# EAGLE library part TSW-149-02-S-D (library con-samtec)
THROUGH-HOLE .025" SQ POST HEADER Source: Samtec TSW.pdf
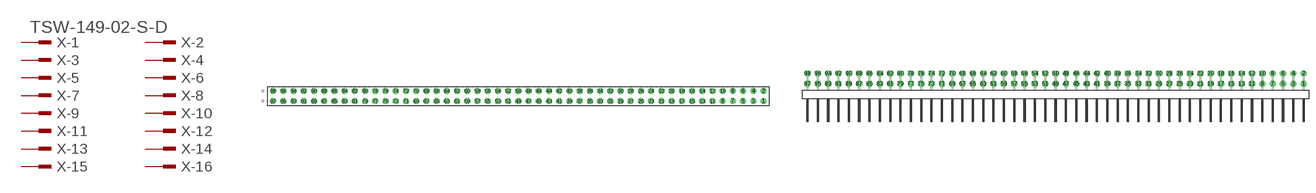
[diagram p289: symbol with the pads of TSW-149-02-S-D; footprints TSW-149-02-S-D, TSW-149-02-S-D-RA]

Designator prefix X; gates -1=MPINV -2=MPIN -3=MPIN -4=MPIN -5=MPIN -6=MPIN -7=MPIN -8=MPIN -9=MPIN -10=MPIN -11=MPIN -12=MPIN -13=MPIN -14=MPIN -15=MPIN -16=MPIN -17=MPIN -18=MPIN -19=MPIN -20=MPIN -21=MPIN -22=MPIN -23=MPIN -24=MPIN -25=MPIN -26=MPIN -27=MPIN -28=MPIN -29=MPIN -30=MPIN -31=MPIN -32=MPIN -33=MPIN -34=MPIN -35=MPIN -36=MPIN -37=MPIN -38=MPIN -39=MPIN -40=MPIN -41=MPIN -42=MPIN -43=MPIN -44=MPIN -45=MPIN -46=MPIN -47=MPIN -48=MPIN -49=MPIN -50=MPIN -51=MPIN -52=MPIN -53=MPIN -54=MPIN -55=MPIN -56=MPIN -57=MPIN -58=MPIN -59=MPIN -60=MPIN -61=MPIN -62=MPIN -63=MPIN -64=MPIN -65=MPIN -66=MPIN -67=MPIN -68=MPIN -69=MPIN -70=MPIN -71=MPIN -72=MPIN -73=MPIN -74=MPIN -75=MPIN -76=MPIN -77=MPIN -78=MPIN -79=MPIN -80=MPIN -81=MPIN -82=MPIN -83=MPIN -84=MPIN -85=MPIN -86=MPIN -87=MPIN -88=MPIN -89=MPIN -90=MPIN -91=MPIN -92=MPIN -93=MPIN -94=MPIN -95=MPIN -96=MPIN -97=MPIN -98=MPIN

## TSW-149-02-S-D (OC_FARNELL: unknown; OC_NEWARK: unknown)  [TSW-149-02-S-D]
1  -1:1  pas
2  -2:1  pas
3  -3:1  pas
4  -4:1  pas
5  -5:1  pas
6  -6:1  pas
7  -7:1  pas
8  -8:1  pas
9  -9:1  pas
10  -10:1  pas
11  -11:1  pas
12  -12:1  pas
13  -13:1  pas
14  -14:1  pas
15  -15:1  pas
16  -16:1  pas
17  -17:1  pas
18  -18:1  pas
19  -19:1  pas
20  -20:1  pas
21  -21:1  pas
22  -22:1  pas
23  -23:1  pas
24  -24:1  pas
25  -25:1  pas
26  -26:1  pas
27  -27:1  pas
28  -28:1  pas
29  -29:1  pas
30  -30:1  pas
31  -31:1  pas
32  -32:1  pas
33  -33:1  pas
34  -34:1  pas
35  -35:1  pas
36  -36:1  pas
37  -37:1  pas
38  -38:1  pas
39  -39:1  pas
40  -40:1  pas
41  -41:1  pas
42  -42:1  pas
43  -43:1  pas
44  -44:1  pas
45  -45:1  pas
46  -46:1  pas
47  -47:1  pas
48  -48:1  pas
49  -49:1  pas
50  -50:1  pas
51  -51:1  pas
52  -52:1  pas
53  -53:1  pas
54  -54:1  pas
55  -55:1  pas
56  -56:1  pas
57  -57:1  pas
58  -58:1  pas
59  -59:1  pas
60  -60:1  pas
61  -61:1  pas
62  -62:1  pas
63  -63:1  pas
64  -64:1  pas
65  -65:1  pas
66  -66:1  pas
67  -67:1  pas
68  -68:1  pas
69  -69:1  pas
70  -70:1  pas
71  -71:1  pas
72  -72:1  pas
73  -73:1  pas
74  -74:1  pas
75  -75:1  pas
76  -76:1  pas
77  -77:1  pas
78  -78:1  pas
79  -79:1  pas
80  -80:1  pas
81  -81:1  pas
82  -82:1  pas
83  -83:1  pas
84  -84:1  pas
85  -85:1  pas
86  -86:1  pas
87  -87:1  pas
88  -88:1  pas
89  -89:1  pas
90  -90:1  pas
91  -91:1  pas
92  -92:1  pas
93  -93:1  pas
94  -94:1  pas
95  -95:1  pas
96  -96:1  pas
97  -97:1  pas
98  -98:1  pas

## TSW-149-02-S-D-RA (OC_FARNELL: unknown; OC_NEWARK: unknown)  [TSW-149-02-S-D-RA]
Pads as for TSW-149-02-S-D

## Footprint TSW-149-02-S-D (pad centres in mm)
THROUGH-HOLE .025" SQ POST HEADER Source: Samtec TSW.pdf
drill 1 pad 1.5 octagon: 1 60.96,-1.27; 2 60.96,1.27; 3 58.42,-1.27; 4 58.42,1.27; 5 55.88,-1.27; 6 55.88,1.27; 7 53.34,-1.27; 8 53.34,1.27; 9 50.8,-1.27; 10 50.8,1.27; 11 48.26,-1.27; 12 48.26,1.27; 13 45.72,-1.27; 14 45.72,1.27; 15 43.18,-1.27; 16 43.18,1.27; 17 40.64,-1.27; 18 40.64,1.27; 19 38.1,-1.27; 20 38.1,1.27; 21 35.56,-1.27; 22 35.56,1.27; 23 33.02,-1.27; 24 33.02,1.27; 25 30.48,-1.27; 26 30.48,1.27; 27 27.94,-1.27; 28 27.94,1.27; 29 25.4,-1.27; 30 25.4,1.27; 31 22.86,-1.27; 32 22.86,1.27; 33 20.32,-1.27; 34 20.32,1.27; 35 17.78,-1.27; 36 17.78,1.27; 37 15.24,-1.27; 38 15.24,1.27; 39 12.7,-1.27; 40 12.7,1.27; 41 10.16,-1.27; 42 10.16,1.27; 43 7.62,-1.27; 44 7.62,1.27; 45 5.08,-1.27; 46 5.08,1.27; 47 2.54,-1.27; 48 2.54,1.27; 49 0,-1.27; 50 0,1.27; 51 -2.54,-1.27; 52 -2.54,1.27; 53 -5.08,-1.27; 54 -5.08,1.27; 55 -7.62,-1.27; 56 -7.62,1.27; 57 -10.16,-1.27; 58 -10.16,1.27; 59 -12.7,-1.27; 60 -12.7,1.27; 61 -15.24,-1.27; 62 -15.24,1.27; 63 -17.78,-1.27; 64 -17.78,1.27; 65 -20.32,-1.27; 66 -20.32,1.27; 67 -22.86,-1.27; 68 -22.86,1.27; 69 -25.4,-1.27; 70 -25.4,1.27; 71 -27.94,-1.27; 72 -27.94,1.27; 73 -30.48,-1.27; 74 -30.48,1.27; 75 -33.02,-1.27; 76 -33.02,1.27; 77 -35.56,-1.27; 78 -35.56,1.27; 79 -38.1,-1.27; 80 -38.1,1.27; 81 -40.64,-1.27; 82 -40.64,1.27; 83 -43.18,-1.27; 84 -43.18,1.27; 85 -45.72,-1.27; 86 -45.72,1.27; 87 -48.26,-1.27; 88 -48.26,1.27; 89 -50.8,-1.27; 90 -50.8,1.27; 91 -53.34,-1.27; 92 -53.34,1.27; 93 -55.88,-1.27; 94 -55.88,1.27; 95 -58.42,-1.27; 96 -58.42,1.27; 97 -60.96,-1.27; 98 -60.96,1.27

## Footprint TSW-149-02-S-D-RA (pad centres in mm)
THROUGH-HOLE .025" SQ POST HEADER Source: Samtec TSW.pdf
drill 1 pad 1.5 octagon: 1 60.96,1.524; 2 60.96,4.064; 3 58.42,1.524; 4 58.42,4.064; 5 55.88,1.524; 6 55.88,4.064; 7 53.34,1.524; 8 53.34,4.064; 9 50.8,1.524; 10 50.8,4.064; 11 48.26,1.524; 12 48.26,4.064; 13 45.72,1.524; 14 45.72,4.064; 15 43.18,1.524; 16 43.18,4.064; 17 40.64,1.524; 18 40.64,4.064; 19 38.1,1.524; 20 38.1,4.064; 21 35.56,1.524; 22 35.56,4.064; 23 33.02,1.524; 24 33.02,4.064; 25 30.48,1.524; 26 30.48,4.064; 27 27.94,1.524; 28 27.94,4.064; 29 25.4,1.524; 30 25.4,4.064; 31 22.86,1.524; 32 22.86,4.064; 33 20.32,1.524; 34 20.32,4.064; 35 17.78,1.524; 36 17.78,4.064; 37 15.24,1.524; 38 15.24,4.064; 39 12.7,1.524; 40 12.7,4.064; 41 10.16,1.524; 42 10.16,4.064; 43 7.62,1.524; 44 7.62,4.064; 45 5.08,1.524; 46 5.08,4.064; 47 2.54,1.524; 48 2.54,4.064; 49 0,1.524; 50 0,4.064; 51 -2.54,1.524; 52 -2.54,4.064; 53 -5.08,1.524; 54 -5.08,4.064; 55 -7.62,1.524; 56 -7.62,4.064; 57 -10.16,1.524; 58 -10.16,4.064; 59 -12.7,1.524; 60 -12.7,4.064; 61 -15.24,1.524; 62 -15.24,4.064; 63 -17.78,1.524; 64 -17.78,4.064; 65 -20.32,1.524; 66 -20.32,4.064; 67 -22.86,1.524; 68 -22.86,4.064; 69 -25.4,1.524; 70 -25.4,4.064; 71 -27.94,1.524; 72 -27.94,4.064; 73 -30.48,1.524; 74 -30.48,4.064; 75 -33.02,1.524; 76 -33.02,4.064; 77 -35.56,1.524; 78 -35.56,4.064; 79 -38.1,1.524; 80 -38.1,4.064; 81 -40.64,1.524; 82 -40.64,4.064; 83 -43.18,1.524; 84 -43.18,4.064; 85 -45.72,1.524; 86 -45.72,4.064; 87 -48.26,1.524; 88 -48.26,4.064; 89 -50.8,1.524; 90 -50.8,4.064; 91 -53.34,1.524; 92 -53.34,4.064; 93 -55.88,1.524; 94 -55.88,4.064; 95 -58.42,1.524; 96 -58.42,4.064; 97 -60.96,1.524; 98 -60.96,4.064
